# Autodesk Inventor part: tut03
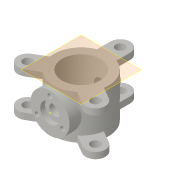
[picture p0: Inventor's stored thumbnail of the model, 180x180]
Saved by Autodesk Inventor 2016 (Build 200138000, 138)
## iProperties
Created: 2015-05
Part Number: tut03
Material: Generic
Document SubType Name: Modeling
Designer: Sandeep
Density: 1 g/cm^3
Appearance: Default
Author: Sandeep
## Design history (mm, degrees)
sketch "Sketch1"
  geometry: 1 further point
sketch "Sketch2"
  geometry: C1 r 140 at (0, 0); C2 r 97 at (0, 0); 1 further point
  constraints: 2 centre point, 2 coincident
  dimensions: "d0" = 194 diameter of C2; "d1" = 280 diameter of C1
extrude "Extrusion1" new body sketch "Sketch2" stored distance "d2" = 225; taper "d3" = 0 deg
workplane "Work Plane1"
sketch "Sketch3"
  geometry: C1 r 100 at (0, 0); 1 further point
  constraints: 1 centre point, 1 coincident
  dimensions: "d5" = 200 diameter of C1
extrude "Extrusion2" join sketch "Sketch3" stored distance "d6" = 225; taper "d7" = 0 deg
workplane "Work Plane2"
sketch "Sketch4"
  geometry: 1 further point
sketch "Sketch5"
  geometry: C1 r 37.5 at (0, 0); 1 further point
  constraints: 1 centre point, 1 coincident
  dimensions: "d9" = 75 diameter of C1
extrude "Extrusion3" join sketch "Sketch5" stored distance "d10" = 225; taper "d11" = 0 deg
sketch "Sketch6"
  geometry: 1 further point
hole "Hole1" diameter "d14" = 56; stored, may be unused: countersink angle "d18" = 90 deg, drill point angle "d20" = 118 deg; dims "d15" = 6, "d16" = 100, "d17" = 25, "d19" = 310, "d23" = 10, "d24" = 10
sketch "Sketch7" dims "d21" = 150
  geometry: 3 further points
  constraints: 1 coincident, 1 vertical alignment, 2 other
hole "Hole3" sketch "Sketch7" at (0, 75) diameter "d31" = 24; stored, may be unused: countersink angle "d35" = 90 deg, drill point angle "d37" = 118 deg; dims "d32" = 6, "d33" = 100, "d34" = 25, "d36" = 15
pattern_circular "Circular Pattern1" dims angle "d39" = 360 deg
workplane "Work Plane3"
sketch "Sketch9"
  geometry: L1 (0, 201.153)-(0, -170.104); L2 (-50, 130.767)-(-50, 200); L3 (50, 200)-(50, 130.767); L4 (50, 130.767)-(50, 130.767); C1 r 23.5 at (0, 200); A1 r 50 centre (0, 200) between (50, 200) and (-50, 200); A2 r 140 centre (0, 0) between (50, 130.767) and (-50, 130.767); 3 further points
  constraints: 8 end point, 5 point on circle, 3 centre point, 2 coincident, 2 point on line, 2 tangent, 2 vertical, 1 midpoint, 4 other
  dimensions: "d42" = 50 radius of A1; "d43" = 200 distance of point (0, 0) A1.centre; "d44" = 47 diameter of C1
extrude "Extrusion4" join sketch "Sketch9" distance "d45" = 32; taper "d46" = 0 deg
pattern_circular "Circular Pattern2" dims angle "d48" = 360 deg
mirror "Mirror1"
body "Solid1"
other parameters: "d8" = 325, "d41" = 0
